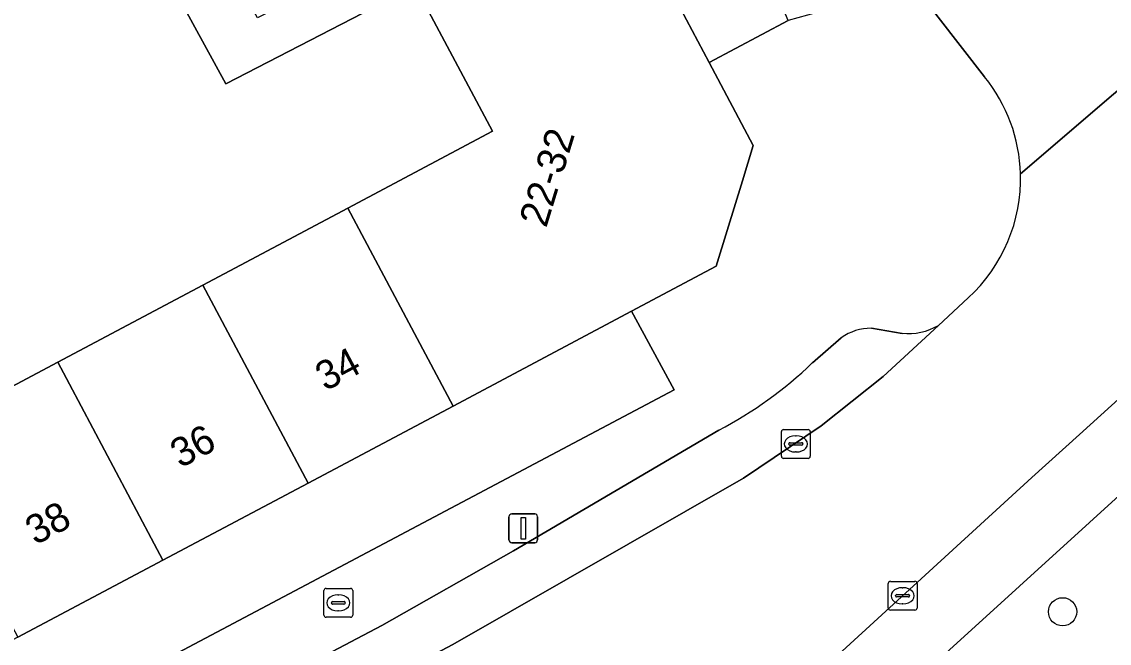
# Model space of a CAD drawing. Extents: x 160304 to 160955, y 383684 to 384161.
# Drawn here: x 160762.28 to 160799.97, y 383873.27 to 383894.83 of the extents above; entities that cross this region are included whole.
import ezdxf

# ---------------------------------------------------------------- set-up
doc = ezdxf.new("R2010")
doc.units = 0
for name, color, linetype in [('IMGEO_Boom', 7, 'Continuous'), ('IMGEO_Brandkraan', 7, 'Continuous'), ('IMGEO_Erf', 7, 'Continuous'), ('IMGEO_Groenvoorziening', 7, 'Continuous'), ('IMGEO_Kolk', 7, 'Continuous'), ('IMGEO_Lichtmast', 7, 'Continuous'), ('IMGEO_Pand', 7, 'Continuous'), ('IMGEO_Pand_nummerreeks', 7, 'Continuous'), ('IMGEO_Parkeervlak_open', 7, 'Continuous'), ('IMGEO_Rijbaan_lokaal_open', 7, 'Continuous'), ('IMGEO_Voetpad_open', 7, 'Continuous')]:
    doc.layers.add(name, color=color, linetype=linetype)

msp = doc.modelspace()

# ---------------------------------------------------------------- linework, layer by layer
at = {"layer": 'IMGEO_Boom'}
msp.add_circle((160798.358, 383874.366), 0.489, dxfattribs=at)
at = {"layer": 'IMGEO_Brandkraan'}
for p, q in [((160772.75, 383874.25), (160772.75, 383875.102)), ((160772.825, 383875.176), (160773.677, 383875.176)), ((160773.238, 383874.956), (160773.263, 383874.956)), ((160773.751, 383875.102), (160773.751, 383874.25)), ((160773.009, 383874.67), (160773.009, 383874.682)), ((160773.447, 383874.633), (160773.049, 383874.633)), ((160773.052, 383874.719), (160773.45, 383874.719)), ((160773.493, 383874.682), (160773.493, 383874.67)), ((160773.261, 383874.396), (160773.236, 383874.396)), ((160773.677, 383874.176), (160772.825, 383874.176))]:
    msp.add_line(p, q, dxfattribs=at)
for points in [[(160772.75, 383874.25), (160772.75, 383875.102)], [(160772.825, 383875.176), (160773.677, 383875.176)], [(160773.751, 383875.102), (160773.751, 383874.25)], [(160773.677, 383874.176), (160772.825, 383874.176)]]:
    msp.add_lwpolyline(points, dxfattribs=at)
for centre, radius, start, end in [((160772.827, 383875.1), 0.0765, 91.552, 178.448), ((160772.827, 383875.1), 0.0765, 91.552, 178.448), ((160773.675, 383875.1), 0.0765, 1.552, 88.448), ((160773.675, 383875.1), 0.0765, 1.552, 88.448), ((160773.049, 383874.679), 0.0403, 85.8775, 175.7526), ((160773.046, 383874.669), 0.0366, 178.938, 274.7102), ((160773.45, 383874.676), 0.043, 264.8664, 352.4533), ((160773.454, 383874.681), 0.0386, 1.7309, 96.639), ((160772.827, 383874.252), 0.0765, 181.552, 268.448), ((160772.827, 383874.252), 0.0765, 181.552, 268.448), ((160773.675, 383874.252), 0.0765, 271.552, 358.448), ((160773.675, 383874.252), 0.0765, 271.552, 358.448)]:
    msp.add_arc(centre, radius, start, end, dxfattribs=at)
for centre, major_axis, ratio, start_param, end_param in [((160773.237, 383874.676), (-0.387, 0.002), 0.722429, 4.712389, 7.853982), ((160773.262, 383874.676), (-0.39, 0.002), 0.717154, 1.570796, 4.712389)]:
    msp.add_ellipse(centre, major_axis=major_axis, ratio=ratio, start_param=start_param, end_param=end_param, dxfattribs=at)
at = {"layer": 'IMGEO_Erf'}
msp.add_lwpolyline([(160758.497, 383880.357), (160763.524, 383883.027), (160768.551, 383885.698), (160773.578, 383888.369), (160778.599, 383891.037), (160775.92, 383896.08), (160769.351, 383892.68), (160764.847, 383900.931)], dxfattribs=at)
msp.add_lwpolyline([(160696.844, 383882.915), (160709.724, 383858.649), (160729.382, 383852.644), (160784.889, 383882.06), (160783.419, 383884.791), (160777.227, 383881.501), (160772.2, 383878.83), (160767.173, 383876.159), (160762.146, 383873.488), (160757.119, 383870.817), (160752.092, 383868.146), (160747.065, 383865.475), (160742.038, 383862.804), (160737.011, 383860.133), (160729.196, 383855.981), (160720.48, 383858.649), (160711.848, 383861.291), (160707.647, 383869.198), (160704.955, 383874.264), (160702.264, 383879.33), (160699.572, 383884.396)], close=True, dxfattribs=at)
at = {"layer": 'IMGEO_Groenvoorziening'}
msp.add_lwpolyline([(160801.716, 383879.67), (160792.011, 383870.839)], dxfattribs=at)
at = {"layer": 'IMGEO_Kolk'}
for p, q in [((160788.61, 383879.762), (160788.61, 383880.614)), ((160788.685, 383880.688), (160789.537, 383880.688)), ((160789.611, 383880.614), (160789.611, 383879.762)), ((160788.912, 383880.231), (160789.31, 383880.231)), ((160789.098, 383880.468), (160789.123, 383880.468)), ((160788.869, 383880.182), (160788.869, 383880.194)), ((160789.307, 383880.145), (160788.909, 383880.145)), ((160789.121, 383879.908), (160789.096, 383879.908)), ((160789.353, 383880.194), (160789.353, 383880.182)), ((160789.537, 383879.688), (160788.685, 383879.688)), ((160792.311, 383874.496), (160792.311, 383875.348)), ((160792.386, 383875.422), (160793.238, 383875.422)), ((160793.312, 383875.348), (160793.312, 383874.496)), ((160792.613, 383874.965), (160793.011, 383874.965)), ((160792.799, 383875.202), (160792.824, 383875.202)), ((160792.57, 383874.916), (160792.57, 383874.928)), ((160793.008, 383874.879), (160792.61, 383874.879)), ((160792.822, 383874.642), (160792.797, 383874.642)), ((160793.054, 383874.928), (160793.054, 383874.916)), ((160793.238, 383874.422), (160792.386, 383874.422))]:
    msp.add_line(p, q, dxfattribs=at)
for points in [[(160788.61, 383879.762), (160788.61, 383880.614)], [(160788.685, 383880.688), (160789.537, 383880.688)], [(160789.611, 383880.614), (160789.611, 383879.762)], [(160789.537, 383879.688), (160788.685, 383879.688)], [(160792.311, 383874.496), (160792.311, 383875.348)], [(160792.386, 383875.422), (160793.238, 383875.422)], [(160793.312, 383875.348), (160793.312, 383874.496)], [(160793.238, 383874.422), (160792.386, 383874.422)]]:
    msp.add_lwpolyline(points, dxfattribs=at)
for centre, radius, start, end in [((160788.687, 383880.612), 0.0765, 91.552, 178.448), ((160788.687, 383880.612), 0.0765, 91.552, 178.448), ((160789.535, 383880.612), 0.0765, 1.552, 88.448), ((160789.535, 383880.612), 0.0765, 1.552, 88.448), ((160788.909, 383880.191), 0.0403, 85.8775, 175.7526), ((160789.314, 383880.193), 0.0386, 1.7309, 96.639), ((160788.906, 383880.181), 0.0366, 178.938, 274.7102), ((160789.31, 383880.188), 0.043, 264.8664, 352.4533), ((160788.687, 383879.764), 0.0765, 181.552, 268.448), ((160788.687, 383879.764), 0.0765, 181.552, 268.448), ((160789.535, 383879.764), 0.0765, 271.552, 358.448), ((160789.535, 383879.764), 0.0765, 271.552, 358.448), ((160792.388, 383875.346), 0.0765, 91.552, 178.448), ((160792.388, 383875.346), 0.0765, 91.552, 178.448), ((160793.236, 383875.346), 0.0765, 1.552, 88.448), ((160793.236, 383875.346), 0.0765, 1.552, 88.448), ((160792.61, 383874.925), 0.0403, 85.8775, 175.7526), ((160793.015, 383874.927), 0.0386, 1.7309, 96.639), ((160792.607, 383874.915), 0.0366, 178.938, 274.7102), ((160793.011, 383874.922), 0.043, 264.8664, 352.4533), ((160792.388, 383874.498), 0.0765, 181.552, 268.448), ((160792.388, 383874.498), 0.0765, 181.552, 268.448), ((160793.236, 383874.498), 0.0765, 271.552, 358.448), ((160793.236, 383874.498), 0.0765, 271.552, 358.448)]:
    msp.add_arc(centre, radius, start, end, dxfattribs=at)
for centre, major_axis, ratio, start_param, end_param in [((160789.097, 383880.188), (-0.387, 0.002), 0.722429, 4.712389, 7.853982), ((160789.122, 383880.188), (-0.39, 0.002), 0.717154, 1.570796, 4.712389), ((160792.798, 383874.922), (-0.387, 0.002), 0.722429, 4.712389, 7.853982), ((160792.823, 383874.922), (-0.39, 0.002), 0.717154, 1.570796, 4.712389)]:
    msp.add_ellipse(centre, major_axis=major_axis, ratio=ratio, start_param=start_param, end_param=end_param, dxfattribs=at)
at = {"layer": 'IMGEO_Lichtmast'}
for p, q in [((160779.167, 383876.861), (160779.167, 383877.661)), ((160779.167, 383877.661), (160779.167, 383876.861)), ((160779.267, 383877.761), (160780.057, 383877.761)), ((160780.057, 383877.761), (160779.267, 383877.761)), ((160780.157, 383877.661), (160780.157, 383876.861)), ((160780.157, 383876.861), (160780.157, 383877.661)), ((160780.057, 383876.761), (160779.267, 383876.761)), ((160779.267, 383876.761), (160780.057, 383876.761))]:
    msp.add_line(p, q, dxfattribs=at)
msp.add_lwpolyline([(160779.587, 383877.636), (160779.737, 383877.636), (160779.737, 383876.886), (160779.587, 383876.886), (160779.587, 383877.636)], dxfattribs=at)
for centre, start, end in [((160779.267, 383877.661), 90, 180), ((160779.267, 383877.661), 90, 180), ((160780.057, 383877.661), 0, 90), ((160780.057, 383877.661), 360, 90), ((160779.267, 383876.861), 180, 270), ((160779.267, 383876.861), 180, 270), ((160780.057, 383876.861), 270, 0), ((160780.057, 383876.861), 270, 0)]:
    msp.add_arc(centre, 0.1, start, end, dxfattribs=at)
at = {"layer": 'IMGEO_Pand'}
for points in [[(160787.636, 383890.542), (160786.11, 383893.415), (160782.762, 383899.716), (160775.92, 383896.08), (160778.599, 383891.037), (160773.578, 383888.369), (160777.227, 383881.501), (160783.419, 383884.791), (160786.352, 383886.349), (160786.733, 383887.593), (160787.26, 383889.314)], [(160773.578, 383888.369), (160768.551, 383885.698), (160772.2, 383878.83), (160777.227, 383881.501)], [(160763.524, 383883.027), (160767.173, 383876.159), (160772.2, 383878.83), (160768.551, 383885.698)], [(160763.524, 383883.027), (160758.497, 383880.357), (160762.146, 383873.488), (160767.173, 383876.159)]]:
    msp.add_lwpolyline(points, close=True, dxfattribs=at)
at = {"layer": 'IMGEO_Parkeervlak_open'}
for points in [[(160732.658, 383851.141), (160732.174, 383850.012), (160731.211, 383849.019), (160731.287, 383848.905), (160754.245, 383861.066), (160756.683, 383862.358), (160777.216, 383873.235), (160787.291, 383879.005), (160789.989, 383880.815), (160792.14, 383882.532), (160794.051, 383884.299)], [(160792.794, 383884.023), (160791.727, 383884.201)], [(160790.686, 383883.872), (160789.682, 383882.997)], [(160786.444, 383880.665), (160782.88, 383878.574), (160779.318, 383876.481), (160774.755, 383873.894), (160733.471, 383852.131)]]:
    msp.add_lwpolyline(points, dxfattribs=at)
for centre, radius, start, end in [((160791.732, 383882.375), 1.826, 90.1473, 124.9301), ((160793.005, 383886.065), 2.052, 264.1131, 300.6547), ((160779.737, 383893.391), 14.385, 297.789, 313.7337)]:
    msp.add_arc(centre, radius, start, end, dxfattribs=at)
at = {"layer": 'IMGEO_Rijbaan_lokaal_open'}
for points in [[(160796.899, 383889.554), (160803.345, 383895.079), (160802.929, 383895.102), (160802.405, 383895.178), (160801.89, 383895.3), (160801.389, 383895.468), (160800.904, 383895.68), (160800.439, 383895.934), (160800, 383896.229), (160799.775, 383896.403), (160799.385, 383896.75), (160799.028, 383897.13), (160798.706, 383897.54), (160794.639, 383904.019)], [(160791.926, 383897.813), (160792.957, 383896.415), (160793.205, 383896.093), (160795.654, 383892.917)], [(160759.485, 383857.081), (160779.737, 383867.831), (160779.795, 383867.863), (160779.949, 383867.937), (160780.109, 383867.996), (160780.274, 383868.041), (160780.442, 383868.071), (160780.612, 383868.086), (160780.783, 383868.086), (160780.953, 383868.07), (160781.121, 383868.04), (160781.245, 383868.005), (160789.328, 383871.488), (160789.367, 383871.552), (160789.683, 383871.981), (160790.036, 383872.381), (160797.285, 383879.019), (160798.938, 383880.511), (160800.417, 383881.852), (160804.344, 383885.43), (160806.491, 383887.45), (160812.588, 383892.383), (160817.111, 383895.531)], [(160803.345, 383895.079), (160796.899, 383889.554)], [(160795.082, 383885.252), (160794.051, 383884.299), (160792.14, 383882.532), (160789.989, 383880.815), (160787.291, 383879.005), (160777.216, 383873.235), (160756.683, 383862.358)]]:
    msp.add_lwpolyline(points, dxfattribs=at)
for centre, radius, start, end in [((160791.303, 383889.394), 5.599, 1.6359, 38.9937), ((160791.293, 383889.387), 5.608, 312.4986, 1.7068)]:
    msp.add_arc(centre, radius, start, end, dxfattribs=at)
at = {"layer": 'IMGEO_Voetpad_open'}
for points in [[(160786.063, 383901.511), (160785.538, 383902.764), (160781.359, 383900.528), (160778.547, 383899.021), (160770.447, 383894.965), (160766.636, 383901.887), (160764.847, 383900.931), (160769.351, 383892.68), (160775.92, 383896.08), (160782.762, 383899.716)], [(160782.762, 383899.716), (160786.11, 383893.415), (160788.843, 383894.871), (160786.063, 383901.511)]]:
    msp.add_lwpolyline(points, close=True, dxfattribs=at)
for points in [[(160795.654, 383892.917), (160793.205, 383896.093), (160788.843, 383894.871), (160786.11, 383893.415), (160787.636, 383890.542), (160787.26, 383889.314), (160786.733, 383887.593), (160786.352, 383886.349), (160783.419, 383884.791), (160784.889, 383882.06), (160729.382, 383852.644), (160709.724, 383858.649), (160696.844, 383882.915), (160693.86, 383881.358), (160692.837, 383880.981), (160692.989, 383880.566)], [(160794.051, 383884.299), (160795.082, 383885.252)], [(160791.727, 383884.201), (160792.794, 383884.023)], [(160789.682, 383882.997), (160790.686, 383883.872)], [(160800.417, 383881.852), (160798.938, 383880.511), (160797.285, 383879.019), (160790.036, 383872.381), (160789.683, 383871.981), (160789.367, 383871.552), (160789.328, 383871.488), (160789.09, 383871.095), (160788.856, 383870.616), (160788.665, 383870.118), (160788.52, 383869.605), (160788.421, 383869.081), (160788.369, 383868.55), (160788.364, 383868.017), (160788.396, 383867.631), (160791.178, 383869.514)], [(160774.755, 383873.894), (160779.318, 383876.481), (160782.88, 383878.574), (160786.444, 383880.665)], [(160792.011, 383870.839), (160801.716, 383879.67)], [(160733.471, 383852.131), (160774.755, 383873.894)]]:
    msp.add_lwpolyline(points, dxfattribs=at)
for centre, radius, start, end in [((160791.303, 383889.394), 5.599, 1.6359, 38.9937), ((160791.293, 383889.387), 5.608, 312.4986, 1.7068), ((160791.732, 383882.375), 1.826, 90.1473, 124.9301), ((160793.005, 383886.065), 2.052, 264.1131, 300.6547), ((160779.737, 383893.391), 14.385, 297.789, 313.7337)]:
    msp.add_arc(centre, radius, start, end, dxfattribs=at)

# ---------------------------------------------------------------- texts
at = {"layer": 'IMGEO_Pand_nummerreeks'}
for s, rotation, p in [('22-32', 72.9719, (160780.457, 383887.656)), ('34', 27.9831, (160772.802, 383882.003)), ('36', 27.9831, (160767.775, 383879.332)), ('38', 27.9831, (160762.75, 383876.662))]:
    msp.add_text(s, height=1, rotation=rotation, dxfattribs=at).set_placement(p)

doc.saveas('drawing.dxf')
